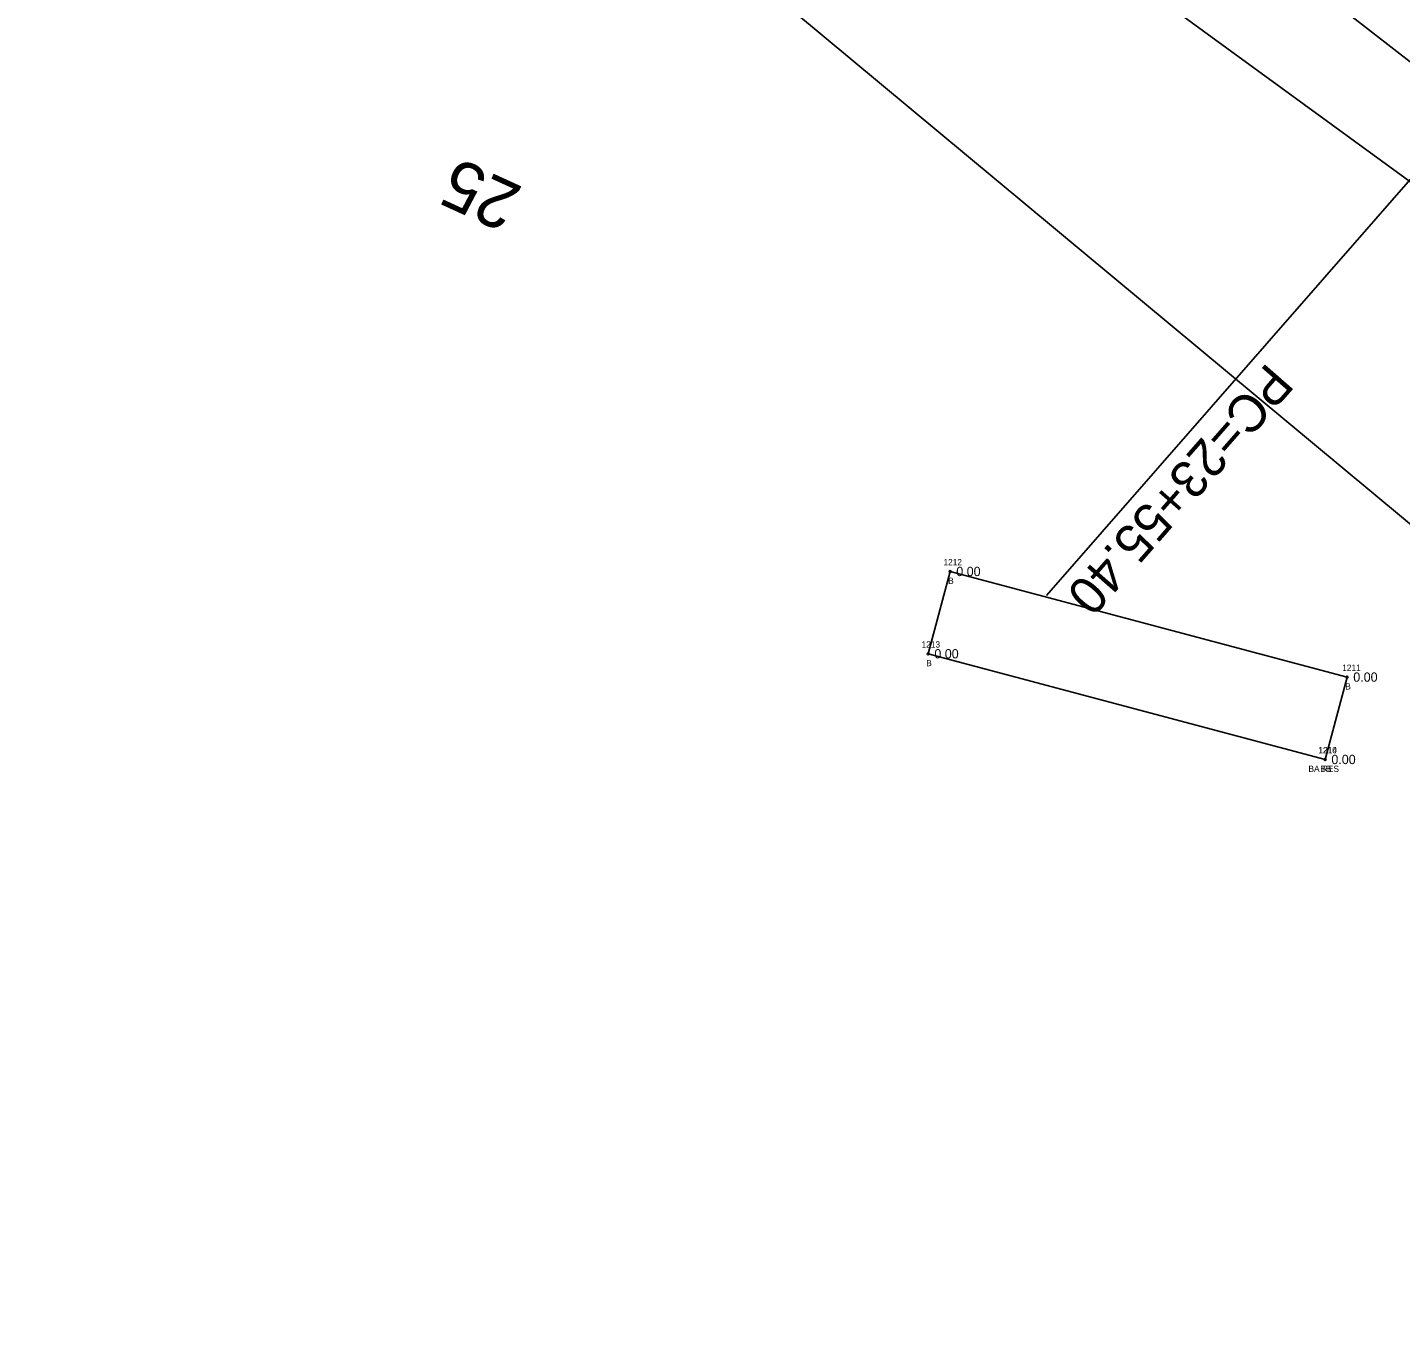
# Model space of a CAD drawing. Extents: x 1393163 to 1398407, y 1072670 to 1074651.
# Drawn here: x 1396650.2 to 1396870.8, y 1074055.8 to 1074266.9 of the extents above; entities that cross this region are included whole.
import ezdxf

# ---------------------------------------------------------------- set-up
doc = ezdxf.new("R2010")
doc.units = 0
for name, color, linetype in [('RD_EX_Bldg', 7, 'Continuous'), ('RD_EX_Bldg_txCode', 7, 'Continuous'), ('RD_EX_Road', 7, 'Continuous'), ('RD_EX_TX_Bldg_ELEV', 7, 'Continuous'), ('RD_EX_VEG', 7, 'Continuous'), ('RD_HC_Cl', 7, 'Continuous'), ('RD_HC_Data', 7, 'Continuous'), ('RD_HC_TX_Sta50', 7, 'Continuous'), ('RD_SMD_Locator', 7, 'Continuous')]:
    doc.layers.add(name, color=color, linetype=linetype)

msp = doc.modelspace()

# ---------------------------------------------------------------- linework, layer by layer
at = {"layer": 'RD_EX_Bldg'}
msp.add_lwpolyline([(1396858.69, 1074149.29), (1396862.21, 1074162.52), (1396798.42, 1074179.49), (1396794.9, 1074166.27), (1396858.69, 1074149.29)], dxfattribs=at)
at = {"layer": 'RD_EX_Road'}
msp.add_lwpolyline([(1397113.03, 1074055.78), (1397073.45, 1074088.2), (1397033.12, 1074122.53), (1397005.07, 1074146.99), (1396959.64, 1074187.05), (1396921.5, 1074220.1), (1396884.1, 1074252.26), (1396844.62, 1074282.93), (1396805.23, 1074308.91), (1396761.89, 1074332.05), (1396716.72, 1074350.46), (1396669.99, 1074363.58), (1396621.68, 1074371.65)], dxfattribs=at)
at = {"layer": 'RD_EX_VEG'}
for points in [[(1396894.17, 1074168.98), (1396933.03, 1074155.57), (1396955.02, 1074151.42), (1396964.49, 1074163.23), (1396875.81, 1074239.54), (1396798.14, 1074296.2), (1396756.06, 1074318.4), (1396711.3, 1074338.97), (1396669.03, 1074354.22), (1396616.02, 1074355.85)], [(1396670.41, 1074284.65), (1396674.99, 1074302.45), (1396722.29, 1074311.92), (1396894.17, 1074168.98)]]:
    msp.add_lwpolyline(points, dxfattribs=at)
at = {"layer": 'RD_HC_Cl'}
msp.add_arc((1396561.57, 1073887.11), 500, 48.8271, 94.0437, dxfattribs=at)
at = {"layer": 'RD_HC_Data'}
msp.add_line((1396890.73, 1074263.47), (1396813.91, 1074175.64), dxfattribs=at)
at = {"layer": 'RD_SMD_Locator'}
for centre in [(1396798.42, 1074179.49), (1396794.9, 1074166.27), (1396862.21, 1074162.52), (1396858.69, 1074149.29), (1396858.69, 1074149.29)]:
    msp.add_circle(centre, 0.15, dxfattribs=at)

# ---------------------------------------------------------------- texts
at = {"layer": 'RD_EX_Bldg_txCode'}
for s, p in [('1212', (1396797.36, 1074180.49)), ('B', (1396798.11, 1074177.49)), ('1213', (1396793.84, 1074167.27)), ('B', (1396794.59, 1074164.27)), ('1211', (1396861.43, 1074163.52)), ('B', (1396861.91, 1074160.52)), ('1210', (1396857.59, 1074150.29)), ('1214', (1396857.63, 1074150.29)), ('BA RES', (1396856.01, 1074147.29)), ('BB', (1396857.91, 1074147.29))]:
    msp.add_text(s, height=1, dxfattribs=at).set_placement(p)
at = {"layer": 'RD_EX_TX_Bldg_ELEV'}
for p in [(1396799.42, 1074178.74), (1396795.9, 1074165.52), (1396863.21, 1074161.77), (1396859.69, 1074148.54), (1396859.69, 1074148.54)]:
    msp.add_text('0.00', height=1.5, dxfattribs=at).set_placement(p)
at = {"layer": 'RD_HC_Data'}
msp.add_text('PC=23+55.40', height=6, rotation=228.8271, dxfattribs=at).set_placement((1396849.45, 1074213.23))
at = {"layer": 'RD_HC_TX_Sta50'}
msp.add_text('25', height=8, rotation=155.3971, dxfattribs=at).set_placement((1396730, 1074241.13))

doc.saveas('drawing.dxf')
